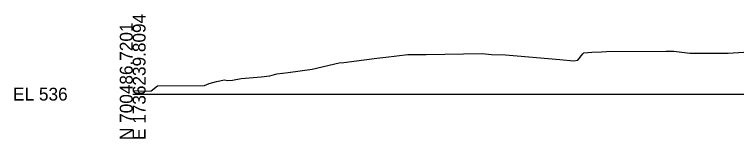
# Model space of a CAD drawing. Extents: x -26 to 803, y -10 to 646.
# Drawn here: x 474.3 to 631.2, y -9.7 to 17.4 of the extents above; entities that cross this region are included whole.
import ezdxf

# ---------------------------------------------------------------- set-up
doc = ezdxf.new("R2010")
doc.units = 0
for name, color, linetype in [('Default', 7, 'Continuous'), ('Exist Cross Section Cell', 7, 'Continuous'), ('Exist XS Ground Line', 7, 'Continuous')]:
    doc.layers.add(name, color=color, linetype=linetype)

msp = doc.modelspace()

# ---------------------------------------------------------------- linework, layer by layer
at = {"layer": 'Exist Cross Section Cell'}
msp.add_line((500, 0), (650, 0), dxfattribs=at)
at = {"layer": 'Exist XS Ground Line'}
for p, q in [((629.41, 8.9), (636.46, 9.43)), ((545.89, 6.91), (553.06, 7.87)), ((553.06, 7.87), (555, 8.03)), ((555, 8.03), (559.82, 8.67)), ((559.82, 8.67), (563.75, 8.65)), ((563.75, 8.65), (575.93, 8.83)), ((575.93, 8.83), (577.93, 8.64)), ((577.93, 8.64), (581.01, 8.54)), ((581.01, 8.54), (592.8, 7.54)), ((596.7, 7.4), (597.84, 8.79)), ((597.84, 8.79), (598, 8.97)), ((598, 8.97), (599.78, 9.12)), ((599.78, 9.12), (601.89, 9.24)), ((601.89, 9.24), (602.93, 9.28)), ((602.93, 9.28), (615.84, 9.33)), ((615.84, 9.33), (617.61, 9.35)), ((617.61, 9.35), (621.07, 8.89)), ((621.07, 8.89), (629.41, 8.9)), ((538.99, 5.44), (544.9, 6.79)), ((544.9, 6.79), (545.89, 6.91)), ((592.8, 7.54), (595.78, 7.28)), ((595.78, 7.28), (596.7, 7.4)), ((531.34, 4.39), (533.76, 4.74)), ((533.76, 4.74), (538.99, 5.44)), ((521.69, 3.06), (523.59, 3.41)), ((523.59, 3.41), (527.93, 3.76)), ((527.93, 3.76), (529.81, 4.02)), ((529.81, 4.02), (531.34, 4.39)), ((503.99, 0.7), (505.39, 1.81)), ((505.39, 1.81), (515.58, 1.91)), ((515.58, 1.91), (516.61, 2.31)), ((516.61, 2.31), (518.19, 2.76)), ((518.19, 2.76), (519.92, 3.09)), ((519.92, 3.09), (520.6, 2.98)), ((520.6, 2.98), (521.69, 3.06)), ((500, 0.78), (502.82, 0.67)), ((502.82, 0.67), (503.99, 0.7))]:
    msp.add_line(p, q, dxfattribs=at)

# ---------------------------------------------------------------- texts
at = {"layer": 'Default'}
msp.add_text('-', height=0.0001, dxfattribs=at).set_placement((500, 0))
msp.add_text('-', height=0.0001, dxfattribs=at).set_placement((500, 0))
at = {"layer": 'Exist Cross Section Cell'}
for s, p in [('E 1736239.8094', (502.8, -10)), ('N 700486.7201', (500, -10))]:
    msp.add_text(s, height=2.8, rotation=90, dxfattribs=at).set_placement(p)
msp.add_text('EL 536', height=2.8, dxfattribs=at).set_placement((474, -1.4))

doc.saveas('drawing.dxf')
